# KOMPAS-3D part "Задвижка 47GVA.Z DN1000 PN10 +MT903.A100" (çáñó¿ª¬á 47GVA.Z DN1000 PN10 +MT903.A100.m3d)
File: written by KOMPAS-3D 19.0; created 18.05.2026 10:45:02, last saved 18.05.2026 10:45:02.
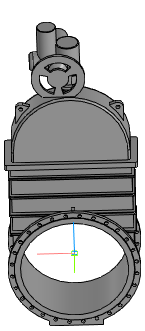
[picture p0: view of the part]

Document properties: Автор: Энергия; Полное имя файла: ..\Задвижка 47GVA.Z DN350_DN1200+MT903.A\Задвижка 47GVA.Z DN1000 PN10 +MT903.A100.a3d

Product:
- Part/product: Задвижка 47GVA.Z DN1000 PN10 +MT903.A100
    Масса: 4788.42
  - Body: Электропривод МТ903.А100 без блока управления
      Масса: 346.451
  - Body: Задвижка 47GVA.Z DN1000 PN10 без исполнит. мех.
      Масса: 4441.97

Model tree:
1. Операция без истории:1
2. Операция без истории:2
